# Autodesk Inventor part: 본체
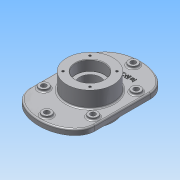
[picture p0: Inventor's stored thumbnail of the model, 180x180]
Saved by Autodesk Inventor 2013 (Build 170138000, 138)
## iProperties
Created: 2015-02
Part Number: 본체
Material: 알루미늄 6061
Document SubType Name: Modeling
Designer: Administrator
Density: 2.71 g/cm^3
Mass: 1660.43 g
Surface Area: 946.614 cm^2
Volume: 612.706 cm^3
Author: Administrator
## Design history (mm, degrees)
sketch "스케치1" dims "d7" = 70
  geometry: L1 (70, 60)-(70, -60); L2 (-70, -60)-(-70, 60); L3 (-70, 110)-(70, -110); L4 (70, 110)-(-70, -110); 5 further points; 2 other entities
  constraints: 8 end point, 4 midpoint, 1 parallel, 8 other
  dimensions: "d4" = 140 distance between parallel lines of L1 L2; "d6" = 120 distance of point (0, -60) point (0, 60)
extrude "돌출1" new body sketch "스케치1" distance "d8" = 12; taper "d9" = 0 deg
sketch "스케치2"
  geometry: C1 r 50 at (0, 0); 1 further point
  constraints: 1 centre point, 1 coincident
  dimensions: "d10" = 100 diameter of C1
extrude "돌출2" join sketch "스케치2" distance "d11" = 35; taper "d12" = 0 deg
sketch "스케치3"
  geometry: C1 r 50 at (0, 0) reference; C2 r 50 at (0, 0)
  constraints: 1 centre point, 1 coincident
  dimensions: "d14" = 100 diameter of C2
extrude "돌출3" join sketch "스케치3" distance "d15" = 23; taper "d16" = 0 deg
sketch "스케치4"
  geometry: C1 r 50 at (0, 0) reference; C2 r 31 at (0, 0)
  constraints: 1 centre point, 1 coincident
  dimensions: "d17" = 62 diameter of C2
extrude "돌출4" cut sketch "스케치4" distance "d18" = 22; taper "d19" = 0 deg
sketch "스케치5"
  geometry: C1 r 50 at (0, 0) reference; C2 r 31 at (0, 0)
  constraints: 1 centre point, 1 coincident
  dimensions: "d20" = 62 diameter of C2
extrude "돌출5" cut sketch "스케치5" distance "d21" = 22; taper "d22" = 0 deg
sketch "스케치6"
  geometry: C1 r 31 at (0, 0) reference; C2 r 22.5 at (0, 0)
  constraints: 1 centre point, 1 coincident
  dimensions: "d23" = 45 diameter of C2
extrude "돌출6" cut sketch "스케치6" stored distance "d24" = 22; taper "d25" = 0 deg
sketch "스케치7"
  geometry: L1 (28.991, 28.991)-(0, 0); L2 (0, 0)-(122.16, 0); C1 r 31 at (0, 0) reference; C2 r 50 at (0, 0) reference
  constraints: 4 end point, 1 horizontal
  dimensions: "d26" = 41 distance of C1.centre L1.start; "d27" = 45 deg angle of L2 L1
hole "구멍1" sketch "스케치7" at (28.991, 28.991) diameter "d28" = 4.917; stored, may be unused: countersink angle "d32" = 90 deg, drill point angle "d34" = 118 deg; dims "d29" = 10, "d30" = 4, "d31" = 2, "d33" = 13
sketch "스케치8"
  geometry: L1 (0, 0)-(93.266, 0); C1 r 31 at (0, 0) reference; C2 r 50 at (0, 0) reference; 1 further point
  constraints: 2 end point, 1 horizontal
  dimensions: "d38" = 41 distance of C1.centre point (28.991, 28.991); "d39" = 45 deg dimension on C1.centre L1.end point (28.991, 28.991)
hole "구멍2" sketch "스케치8" at (28.991, 28.991) diameter "d40" = 4.917; stored, may be unused: countersink angle "d44" = 90 deg, drill point angle "d46" = 118 deg; dims "d41" = 10, "d42" = 4, "d43" = 2, "d45" = 13
sketch "스케치9"
  geometry: L1 (70, -60)-(70, 60) reference; L2 (-70, 60)-(-70, -60) reference; L3 (70, -60)-(70, 60) reference; L4 (-70, 60)-(-70, -60) reference; L5 (53, 60)-(53, -60); L6 (-53, -60)-(-53, 60); L7 (-80.54, 46.5)-(80.54, 46.5); L8 (-80.54, -46.5)-(80.54, -46.5); C1 r 50 at (0, 0) reference; C2 r 50 at (0, 0) reference; C3 r 10 at (0, 93); C4 r 10 at (-80.54, 46.5); C5 r 10 at (-80.54, -46.5); C6 r 10 at (0, -93); C7 r 10 at (80.54, -46.5); C8 r 10 at (80.54, 46.5); C9 r 10 at (-53, 46.5); C10 r 10 at (53, 46.5); C11 r 10 at (53, -46.5); C12 r 10 at (-53, -46.5); A1 r 93 centre (0, 0) between (0, 93) and (-80.54, 46.5); 4 further points; 4 other entities
  constraints: 11 centre point, 8 end point, 8 point on line, 4 parallel, 3 point on circle, 1 coincident, 1 horizontal alignment, 1 perpendicular, 1 vertical alignment, 23 other
  dimensions: "d50" = 17 distance between parallel lines of L1 L5; "d51" = 20 diameter of C3; "d55" = 360 deg dimension on A1.centre C3.centre (derived); "d57" = 20 diameter of C9; "d58" = 20 diameter of C10; "d59" = 20 diameter of C11; "d60" = 20 diameter of C12
extrude "돌출7" join sketch "스케치9" distance "d61" = 5; taper "d62" = 0 deg
sketch "스케치10"
  geometry: C1 r 10 at (0, 0) reference; C2 r 5.5 at (0, 0); 1 further point
  constraints: 1 centre point, 1 coincident
  dimensions: "d64" = 11 diameter of C2
extrude "돌출8" cut sketch "스케치10" stored distance "d65" = 5; taper "d66" = 0 deg
sketch "스케치11"
  geometry: C1 r 10 at (0, 0) reference; C2 r 5.5 at (0, 0); 1 further point
  constraints: 1 centre point, 1 coincident
  dimensions: "d67" = 11 diameter of C2
extrude "돌출9" cut sketch "스케치11" stored distance "d68" = 5; taper "d69" = 0 deg
sketch "스케치12"
  geometry: C1 r 10 at (0, 0) reference; C2 r 5.5 at (0, 0); 1 further point
  constraints: 1 centre point, 1 coincident
  dimensions: "d70" = 11 diameter of C2
extrude "돌출10" cut sketch "스케치12" stored distance "d71" = 5; taper "d72" = 0 deg
sketch "스케치13"
  geometry: C1 r 10 at (0, 0) reference; C2 r 5.5 at (0, 0); 1 further point
  constraints: 1 centre point, 1 coincident
  dimensions: "d73" = 11 diameter of C2
extrude "돌출11" cut sketch "스케치13" stored distance "d74" = 5; taper "d75" = 0 deg
sketch "스케치14"
  geometry: C1 r 10 at (0, 0) reference; C2 r 5.5 at (0, 0); 1 further point
  constraints: 1 centre point, 1 coincident
  dimensions: "d76" = 11 diameter of C2
extrude "돌출12" cut sketch "스케치14" stored distance "d77" = 11; taper "d78" = 0 deg
sketch "스케치15"
  geometry: C1 r 10 at (0, 0) reference; C2 r 5.5 at (0, 0); 1 further point
  constraints: 1 centre point, 1 coincident
  dimensions: "d79" = 11 diameter of C2
extrude "돌출13" cut sketch "스케치15" stored distance "d81" = 11; taper "d82" = 0 deg
fillet "모깎기1" dims "d83" = 0.3
chamfer "모따기1" distance "d84" = 1; stored, may be unused: second distance "d85" = 2, angle "d86" = 45 deg
fillet "모깎기2" dims "d87" = 3
fillet "모깎기3" dims "d88" = 3
sketch "스케치16"
  geometry: C1 r 53 at (0, 0) reference; 1 further point
  constraints: 1 vertical alignment, 1 other
  dimensions: "d89" = 65 distance of C1.centre point (0, 65)
feature "엠보싱1" sketch "스케치16" dims "d90" = 1, "d91" = 0
node "솔리드1"
pattern_circular "원형 패턴1" dims "d22" = 0, angle "d36" = 360 deg
pattern_circular "원형 패턴2" dims angle "d48" = 360 deg
node "투영된 루프1"
